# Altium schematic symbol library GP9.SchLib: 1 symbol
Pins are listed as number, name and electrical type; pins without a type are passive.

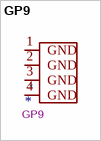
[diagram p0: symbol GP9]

## GP9
designator *  Reference: GP9
pins: 1 GND, 2 GND, 3 GND, 4 GND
